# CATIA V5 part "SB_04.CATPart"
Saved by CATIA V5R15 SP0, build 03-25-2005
Part number: SB_04
Material "Green Blue": density 7860 kg/m3, Young's modulus 2e+11 Pa, Poisson ratio 0.266
Bounding box of the stored display mesh (mm): x 0 to 79, y 0 to 316, z 0 to 49.2
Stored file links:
  E:\#01 CATIA Lecture Materials\#06 DMU\#11 DMU Page01 KIN EX11\SB_04.CATPart
  C:\Program Files\Dassault Systemes\B20\win_b64\startup\materials\Catalog.CATMaterial
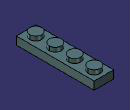
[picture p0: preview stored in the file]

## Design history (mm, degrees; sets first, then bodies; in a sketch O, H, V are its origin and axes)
Body1 (main body), material "Green Blue"
  Sketch1 on xy-plane, origin (0, 0, 0), H (1, 0, 0), V (0, 1, 0)
    circle A1 centre (39.5, 39.5) radius 24.5
    point P1 (39.5, 39.5)
    radius A1 = 24.5
    distance P1 H = 39.5
    distance P1 V = 39.5
  Pad1: profile Sketch1, direction (0, 0, 1), length 49.2
  RectPattern1: of Pad1, direction 1 instances 4, spacing 79, along yz-plane
  Sketch2 on xy-plane, origin (0, 0, 0), H (1, 0, 0), V (0, 1, 0)
    point P1 (0, 316)
    line L1 (0, 316) -> (79, 316)
    line L2 (79, 316) -> (79, 0)
    line L3 (79, 0) -> (0, 0)
    line L4 (0, 0) -> (0, 316)
    point P3 (79, 0)
    distance L2 L4 = 79
    distance L1 L3 = 316 {= RectPattern1.Nb1 * 79mm}
    coincidence: P1 V, P3 H
    horizontal: L1 H, L3 H
    vertical: L2 V, L4 V
  Pad2: profile Sketch2, direction (0, 0, 1), length 32
  Shell1: ExtOffset 0, Face face of Pad2, IntOffset 15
